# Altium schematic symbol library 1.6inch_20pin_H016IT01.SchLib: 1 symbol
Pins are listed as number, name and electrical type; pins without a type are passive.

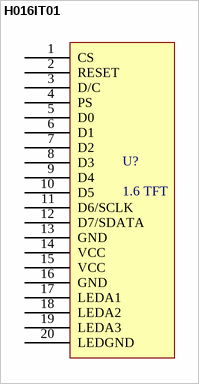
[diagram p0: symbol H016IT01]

## H016IT01
designator U?, comment 1.6 TFT
1.6 TFT LCD
pins: 1 CS, 2 RESET, 3 D/C, 4 PS, 5 D0, 6 D1, 7 D2, 8 D3, 9 D4, 10 D5, 11 D6/SCLK, 12 D7/SDATA, 13 GND, 14 VCC, 15 VCC, 16 GND, 17 LEDA1, 18 LEDA2, 19 LEDA3, 20 LEDGND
